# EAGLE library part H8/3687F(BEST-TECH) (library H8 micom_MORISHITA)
H8/3687F micom board (BestTechnology) Producted by BestTechnology store infomation: http://www.besttechnology.co.jp/
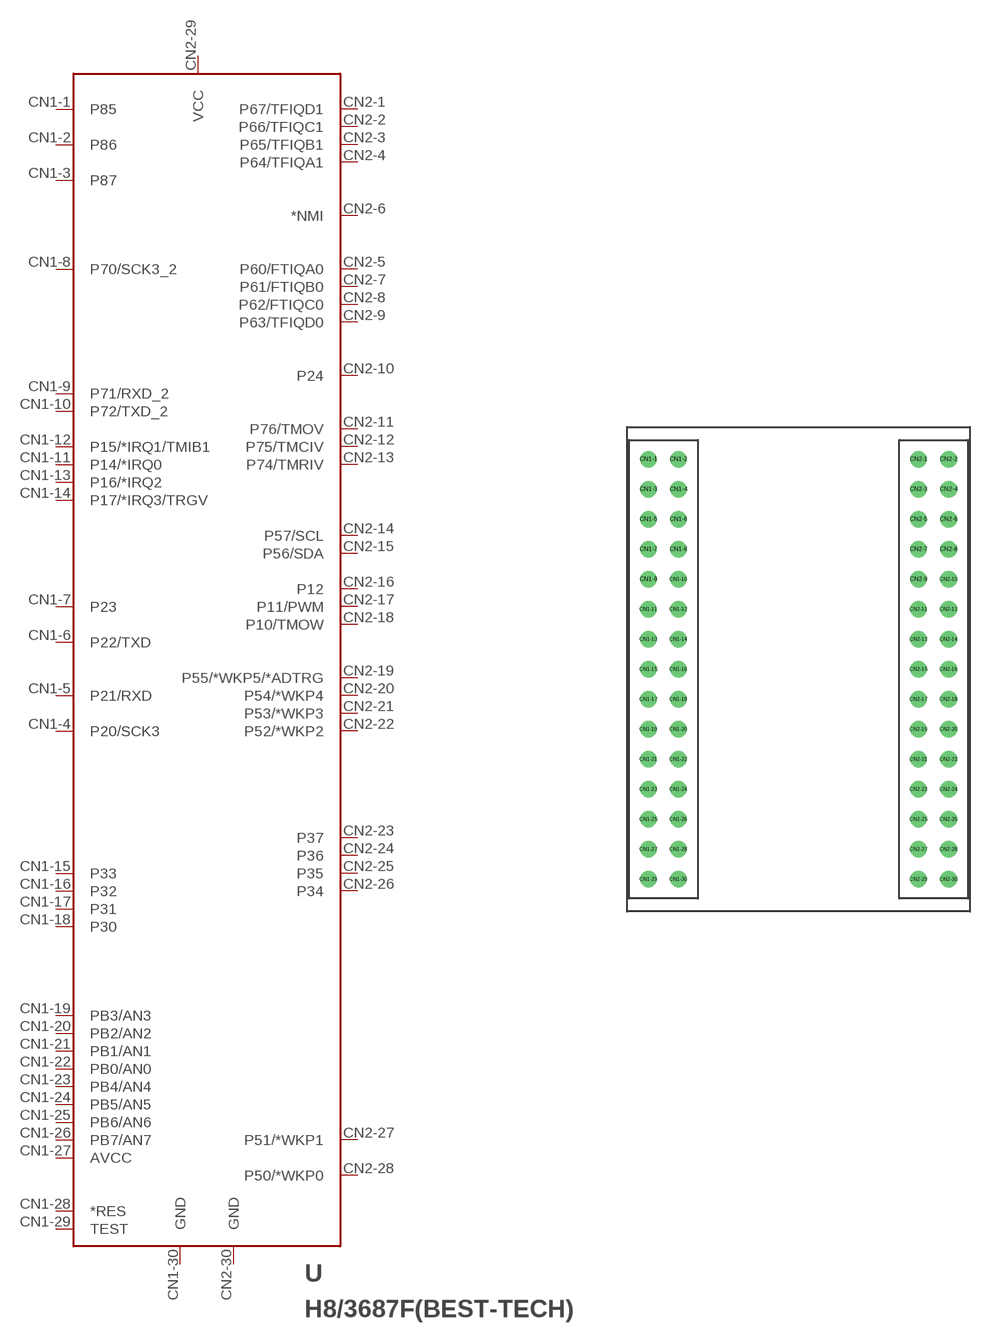
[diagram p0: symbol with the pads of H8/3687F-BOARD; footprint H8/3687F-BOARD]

Designator prefix U

## H8/3687F(BEST-TECH)  [H8/3687F-BOARD]
CN1-1  P85
CN1-2  P86
CN1-3  P87
CN1-4  P20/SCK3
CN1-5  P21/RXD
CN1-6  P22/TXD
CN1-7  P23
CN1-8  P70/SCK3_2
CN1-9  P71/RXD_2
CN1-10  P72/TXD_2
CN1-11  P14/*IRQ0
CN1-12  P15/*IRQ1/TMIB1
CN1-13  P16/*IRQ2
CN1-14  P17/*IRQ3/TRGV
CN1-15  P33
CN1-16  P32
CN1-17  P31
CN1-18  P30
CN1-19  PB3/AN3  in
CN1-20  PB2/AN2  in
CN1-21  PB1/AN1  in
CN1-22  PB0/AN0  in
CN1-23  PB4/AN4  in
CN1-24  PB5/AN5  in
CN1-25  PB6/AN6  in
CN1-26  PB7/AN7  in
CN1-27  AVCC  in
CN1-28  *RES  nc
CN1-29  TEST  nc
CN1-30  GND  pwr
CN2-1  P67/TFIQD1
CN2-2  P66/TFIQC1
CN2-3  P65/TFIQB1
CN2-4  P64/TFIQA1
CN2-5  P60/FTIQA0
CN2-6  *NMI
CN2-7  P61/FTIQB0
CN2-8  P62/FTIQC0
CN2-9  P63/TFIQD0
CN2-10  P24
CN2-11  P76/TMOV
CN2-12  P75/TMCIV
CN2-13  P74/TMRIV
CN2-14  P57/SCL
CN2-15  P56/SDA
CN2-16  P12
CN2-17  P11/PWM
CN2-18  P10/TMOW
CN2-19  P55/*WKP5/*ADTRG
CN2-20  P54/*WKP4
CN2-21  P53/*WKP3
CN2-22  P52/*WKP2
CN2-23  P37
CN2-24  P36
CN2-25  P35
CN2-26  P34
CN2-27  P51/*WKP1
CN2-28  P50/*WKP0
CN2-29  VCC  pwr
CN2-30  GND  pwr

## Footprint H8/3687F-BOARD (pad centres in mm)
H8/3687F micom board (Producted by BestTechnology.Co.)
drill 0.9 round: CN1-1 -12.7,17.78; CN1-2 -10.16,17.78; CN1-3 -12.7,15.24; CN1-4 -10.16,15.24; CN1-5 -12.7,12.7; CN1-6 -10.16,12.7; CN1-7 -12.7,10.16; CN1-8 -10.16,10.16; CN1-9 -12.7,7.62; CN1-10 -10.16,7.62; CN1-11 -12.7,5.08; CN1-12 -10.16,5.08; CN1-13 -12.7,2.54; CN1-14 -10.16,2.54; CN1-15 -12.7,0; CN1-16 -10.16,0; CN1-17 -12.7,-2.54; CN1-18 -10.16,-2.54; CN1-19 -12.7,-5.08; CN1-20 -10.16,-5.08; CN1-21 -12.7,-7.62; CN1-22 -10.16,-7.62; CN1-23 -12.7,-10.16; CN1-24 -10.16,-10.16; CN1-25 -12.7,-12.7; CN1-26 -10.16,-12.7; CN1-27 -12.7,-15.24; CN1-28 -10.16,-15.24; CN1-29 -12.7,-17.78; CN1-30 -10.16,-17.78; CN2-1 10.16,17.78; CN2-2 12.7,17.78; CN2-3 10.16,15.24; CN2-4 12.7,15.24; CN2-5 10.16,12.7; CN2-6 12.7,12.7; CN2-7 10.16,10.16; CN2-8 12.7,10.16; CN2-9 10.16,7.62; CN2-10 12.7,7.62; CN2-11 10.16,5.08; CN2-12 12.7,5.08; CN2-13 10.16,2.54; CN2-14 12.7,2.54; CN2-15 10.16,0; CN2-16 12.7,0; CN2-17 10.16,-2.54; CN2-18 12.7,-2.54; CN2-19 10.16,-5.08; CN2-20 12.7,-5.08; CN2-21 10.16,-7.62; CN2-22 12.7,-7.62; CN2-23 10.16,-10.16; CN2-24 12.7,-10.16; CN2-25 10.16,-12.7; CN2-26 12.7,-12.7; CN2-27 10.16,-15.24; CN2-28 12.7,-15.24; CN2-29 10.16,-17.78; CN2-30 12.7,-17.78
